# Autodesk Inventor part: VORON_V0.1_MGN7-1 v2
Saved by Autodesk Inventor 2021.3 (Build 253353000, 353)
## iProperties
Created: 2022-12
Part Number: VORON_V0.1_MGN7-1 v2
Material: Generic
Document SubType Name: Modeling
Designer: Administrator
Density: 1 g/cm^3
Appearance: Default
Title: VORON_V0.1_MGN7-1 v2
Author: Administrator
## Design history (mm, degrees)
feature "Body1"
body "Solid1"
